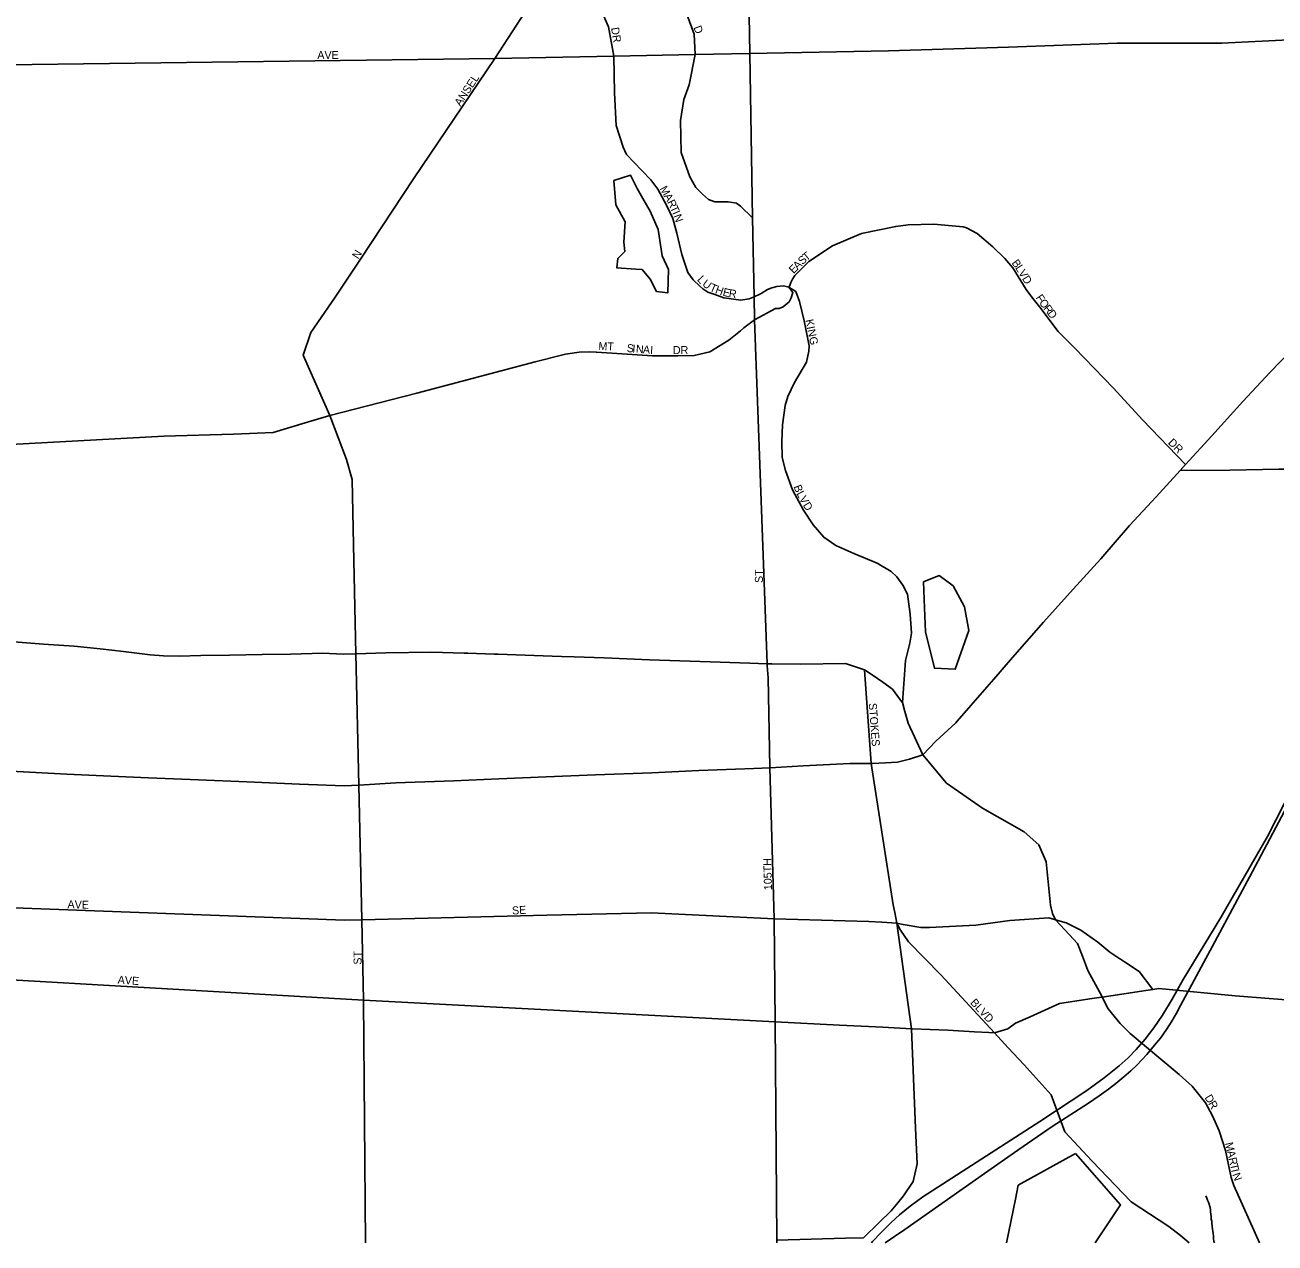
# Model space of a CAD drawing. Extents: x 2139079 to 2262683, y 1235796 to 1334992.
# Drawn here: x 2206334 to 2214145, y 1274636 to 1282247 of the extents above; entities that cross this region are included whole.
import ezdxf

# ---------------------------------------------------------------- set-up
doc = ezdxf.new("R2010")
doc.units = 0
for name, color, linetype in [('GM_P_County_Alignment', 7, 'Continuous'), ('GM_X_City_Street', 7, 'Continuous'), ('GM_X_City_Street_Text', 7, 'Continuous'), ('GM_X_Minor_Lake', 7, 'Continuous'), ('GM_X_Minor_River', 7, 'Continuous'), ('GM_X_Rail_Line', 7, 'Continuous'), ('GM_X_US_Route', 7, 'Continuous')]:
    doc.layers.add(name, color=color, linetype=linetype)

msp = doc.modelspace()

# ---------------------------------------------------------------- linework, layer by layer
at = {"layer": 'GM_P_County_Alignment'}
msp.add_lwpolyline([(2211031.7, 1274654.4), (2211460.5, 1274666.7), (2211573.9, 1274668.7), (2211671.9, 1274763.9), (2211746.1, 1274836.2), (2211789.1, 1274887), (2211823.4, 1274930.1), (2211884.9, 1275020), (2211909.4, 1275130.5), (2211898.6, 1275354.3), (2211874.7, 1275974.6), (2211782.7, 1276635.3)], dxfattribs=at)
at = {"layer": 'GM_X_City_Street'}
for points in [[(2210972.8, 1278241.7), (2210972, 1278255.2), (2210892.3, 1280405), (2210889.7, 1280548.6), (2210881, 1281042.6), (2210862.8, 1282067.9), (2210825, 1284197), (2210780.6, 1287483.9)], [(2209270.3, 1282037), (2209432.8, 1282288), (2209595.7, 1282515.8), (2209677.2, 1282890.1), (2209742.5, 1283166.8), (2209752.1, 1283253), (2209726.2, 1283296.9), (2208926.9, 1283918)], [(2210933.5, 1280568.8), (2210926.7, 1280564.6), (2210889.7, 1280548.6), (2210859.1, 1280535.3), (2210807.1, 1280526.4), (2210700.5, 1280542.6), (2210643.9, 1280562.9), (2210601.6, 1280576.7), (2210569, 1280597.8), (2210550, 1280614.7), (2210509, 1280653.6), (2210476, 1280701.1), (2210437.6, 1280812.6), (2210406.8, 1280946.4), (2210382.8, 1281038.1), (2210345.2, 1281117.6), (2210288.9, 1281220.7), (2210245.6, 1281280), (2210188.4, 1281337), (2210092.1, 1281437.3), (2210072.8, 1281482.5), (2210028.2, 1281618.7), (2210017, 1281821.9), (2210013.1, 1282051.4), (2209981.3, 1282234.9), (2209883.1, 1282460.4)], [(2210881, 1281042.6), (2210804.8, 1281114.2), (2210779.7, 1281133.2), (2210728.9, 1281141), (2210644.1, 1281141), (2210605, 1281156.6), (2210568.2, 1281190.1), (2210525.2, 1281231.4), (2210487.9, 1281297.3), (2210434.3, 1281449.1), (2210429.8, 1281650), (2210451, 1281781.7), (2210483.4, 1281873.3), (2210522.2, 1282061.3), (2210514.6, 1282190.3), (2210442.1, 1282386.7)], [(2209270.3, 1282037), (2209270.3, 1282037), (2210013.1, 1282051.4), (2210522.2, 1282061.3), (2210862.8, 1282067.9), (2211729.6, 1282084.6), (2212480.7, 1282108.6), (2213159.1, 1282132.6), (2213813.3, 1282132.4), (2214273.8, 1282156.6), (2214283.9, 1282105.5)], [(2202934.1, 1281951.1), (2204247.1, 1281973.2), (2205000.4, 1281982.7), (2205895, 1281994.1), (2209270.3, 1282037)], [(2208257.5, 1280525), (2208258.7, 1280526.8), (2208434, 1280789.6), (2208761.2, 1281286.2), (2209270.3, 1282037)], [(2210892.3, 1280405), (2211024.7, 1280475.3), (2211046.8, 1280475.3), (2211072.2, 1280485.8), (2211109.1, 1280516.4), (2211122.8, 1280542.7), (2211132.3, 1280574.4), (2211108.1, 1280609.1), (2211112.5, 1280619.4), (2211116.7, 1280631.7), (2211119.1, 1280638.4), (2211130.5, 1280658.9), (2211143.9, 1280680.5), (2211160.4, 1280698), (2211232.4, 1280769), (2211380.5, 1280867.7), (2211561.4, 1280943), (2211775.6, 1280988.4), (2211852.2, 1280997.9), (2212013.7, 1281003.1), (2212196.9, 1280984.9), (2212218, 1280978.6), (2212284.9, 1280942.8), (2212382.8, 1280859.8), (2212456.4, 1280788.6), (2212507, 1280729.5), (2212590.5, 1280593.7)], [(2211818, 1278012.4), (2211836.4, 1278276.2), (2211864.2, 1278383.1), (2211872.9, 1278447.4), (2211864.5, 1278565.6), (2211847.9, 1278689.6), (2211820.6, 1278747.2), (2211781.5, 1278798.6), (2211746.8, 1278832), (2211659.5, 1278884.3), (2211514.1, 1278943.5), (2211400.8, 1278995.3), (2211325.6, 1279045.9), (2211259.9, 1279122.8), (2211197.9, 1279215.7), (2211129.2, 1279342.7), (2211086.6, 1279462.2), (2211064.9, 1279543.9), (2211062.8, 1279644.2), (2211066.7, 1279748.6), (2211083.5, 1279869.2), (2211101.5, 1279925.1), (2211142.7, 1280012.6), (2211216.6, 1280139.2), (2211231.4, 1280207.8), (2211233.5, 1280242.6), (2211202.4, 1280399), (2211174.2, 1280518.8), (2211151, 1280580.6), (2211108.1, 1280609.1), (2211073.2, 1280616.6), (2211032.7, 1280612.3), (2211001.5, 1280605), (2210974.4, 1280593.5), (2210933.5, 1280568.8)], [(2212590.5, 1280593.7), (2212590.9, 1280593.2), (2212593.8, 1280588.5), (2212635.1, 1280535.5), (2212676.7, 1280483), (2212789.6, 1280332.2), (2212895.1, 1280226.7), (2213136.2, 1279977.8), (2213316.8, 1279778.7), (2213586.8, 1279500.2)], [(2208237.8, 1279806.9), (2208073.1, 1280183.7), (2208120.3, 1280325), (2208249.8, 1280513.5), (2208257.5, 1280525)], [(2210355.4, 1280180.2), (2210414.2, 1280180.4), (2210516.4, 1280182.2), (2210614.3, 1280204), (2210733.3, 1280276.3), (2210804.5, 1280335.8), (2210826.2, 1280354.2), (2210892.3, 1280405)], [(2205419.6, 1279573.1), (2205635, 1279607.5), (2205936.3, 1279607.8), (2207201.4, 1279677.6), (2207637.1, 1279689.3), (2207884.5, 1279701), (2208084.7, 1279759.8), (2208237.8, 1279806.9), (2208782.5, 1279945.6), (2209521.7, 1280141), (2209712.5, 1280189.9), (2209796.2, 1280201.6), (2209859.5, 1280204.6), (2209902.3, 1280201.9)], [(2209902.3, 1280201.9), (2209904.6, 1280201.8), (2210255.9, 1280180), (2210354.8, 1280180.2), (2210355.4, 1280180.2)], [(2208460.8, 1274636.1), (2208449.7, 1276154.3), (2208438.4, 1276656.1), (2208419.5, 1277497.5), (2208401.1, 1278318.3), (2208385.8, 1278997.7), (2208377.6, 1279406.5), (2208342, 1279530.8), (2208237.8, 1279806.9)], [(2210987.8, 1277609.3), (2210977.4, 1278166.4), (2210972.8, 1278241.7)], [(2211580.7, 1278217.2), (2211622.4, 1277632), (2211758.5, 1276749.9), (2211769, 1276700.4), (2211782.7, 1276635.3), (2211788.8, 1276622.7)], [(2212773.3, 1276655.7), (2212773.3, 1276655.7), (2212754.2, 1276693.9), (2212743.5, 1276746.6), (2212715.9, 1277016.7), (2212669.6, 1277124.1), (2212577.8, 1277204.4), (2212316.5, 1277353.2), (2212092.6, 1277509.2), (2211944.8, 1277686.4)], [(2211015.8, 1276660.8), (2210987.9, 1277605.5), (2210987.8, 1277609.3)], [(2195316.8, 1275884.2), (2195584.4, 1275925.4), (2195898.5, 1275973.8), (2196857.5, 1276121.5), (2198055.8, 1276306.1), (2199423.7, 1276514.9), (2199975.3, 1276599.1), (2200548.3, 1276694.8), (2200960.1, 1276758.7), (2204353.6, 1276802.7), (2205985.7, 1276739.7), (2208329.5, 1276653.5), (2208438.4, 1276656.1), (2209594.3, 1276683.5), (2210249.4, 1276698.5), (2211015.8, 1276660.8), (2211607.3, 1276645.7), (2211689.1, 1276641.1), (2211782.7, 1276635.3), (2211800.4, 1276631.3)], [(2211031.9, 1274636.1), (2211031.7, 1274654.4), (2211022.8, 1276017.2), (2211015.8, 1276660.8)], [(2211800.4, 1276631.3), (2211821.9, 1276626.4), (2211931.5, 1276607.9), (2211986.4, 1276606.6), (2212275.9, 1276621.7), (2212489.2, 1276652.2), (2212733, 1276667.3), (2212773.3, 1276655.7), (2212839.7, 1276636.8), (2212931, 1276591), (2213037.6, 1276514.8), (2213113.9, 1276453.8), (2213176.3, 1276412.1), (2213179.8, 1276409.8)], [(2212961.4, 1276378.4), (2212954.7, 1276395.9), (2212942.5, 1276427.7), (2212910.8, 1276507.3), (2212861.6, 1276562.5), (2212773.3, 1276655.7)], [(2211788.8, 1276622.7), (2211804.8, 1276589.9), (2211854.3, 1276518.4), (2212057.6, 1276311.5), (2212391.8, 1275950.1)], [(2195173.4, 1275563.7), (2195259.9, 1275543.1), (2195320.8, 1275531.8), (2195348.8, 1275529.9), (2195377.3, 1275531.8), (2196923.8, 1275769.9), (2197062.7, 1275778.9), (2197588.4, 1275813.1), (2197889.7, 1275856.3), (2199487.9, 1276121.4), (2200965.1, 1276364.1), (2204362.3, 1276390.1), (2205993.3, 1276295), (2208449.7, 1276154.3), (2211022.8, 1276017.2), (2211423.6, 1275997.3), (2211694.1, 1275984), (2211874.7, 1275974.6), (2211880.2, 1275974.3), (2212100, 1275965.1), (2212268.1, 1275954.8), (2212357.1, 1275951.5)], [(2214048.2, 1274636.1), (2213887.9, 1274995.1), (2213871.4, 1275045.1), (2213836, 1275213.4), (2213796.8, 1275337.5), (2213754, 1275431.4), (2213711.2, 1275511.4), (2213628.2, 1275615), (2213547.4, 1275688.6), (2213240.8, 1275945), (2213178.2, 1276008.6), (2213103.3, 1276098.3), (2213065.4, 1276172.6), (2213060.5, 1276182.3), (2212976.6, 1276338.7), (2212961.4, 1276378.4)], [(2213179.8, 1276409.8), (2213205.2, 1276392.9), (2213296.7, 1276331.9), (2213382.1, 1276220.8)], [(2213032.7, 1276167.6), (2213065.4, 1276172.6), (2213311.4, 1276210.1), (2213337.5, 1276214.1)], [(2213337.5, 1276214.1), (2213382.1, 1276220.8), (2213419.2, 1276226.5), (2213896.2, 1276179.9), (2214242.7, 1276154.3), (2214292.4, 1276150.6), (2214344.4, 1276150.8), (2214360.8, 1276150.8)], [(2212357.1, 1275951.5), (2212391.8, 1275950.1), (2212476.2, 1275974.6), (2212523.3, 1276009.3), (2212616.1, 1276049.6), (2212798.1, 1276131.9), (2213003.4, 1276163.2), (2213032.7, 1276167.6)], [(2212391.8, 1275950.1), (2212478.7, 1275855.8), (2212577.8, 1275749.3), (2212746.2, 1275561), (2212831.4, 1275329.9), (2213003.7, 1275146.8), (2213246.4, 1274893.7), (2213482, 1274738.8), (2213553.9, 1274682.9), (2213609.4, 1274636.1)]]:
    msp.add_lwpolyline(points, dxfattribs=at)
at = {"layer": 'GM_X_Minor_Lake'}
msp.add_line((2212523.2, 1274910.1), (2212467.9, 1274636.1), dxfattribs=at)
for points in [[(2210194.7, 1281162), (2210160.1, 1281224), (2210118.3, 1281307.6), (2210014.5, 1281275.4)], [(2210014.5, 1281275.4), (2210025.6, 1281123), (2210084, 1281017.7), (2210076.6, 1280889), (2210081.8, 1280830.8), (2210038.5, 1280787.8), (2210031.7, 1280729.4), (2210150.3, 1280721.7), (2210190.5, 1280718.4), (2210239.9, 1280659.1), (2210279.7, 1280581.6), (2210350.1, 1280572.9), (2210355.2, 1280719.6), (2210315.3, 1280803.2), (2210289.8, 1280969.4), (2210241.3, 1281083), (2210194.7, 1281162)], [(2211955.7, 1278605.4), (2211961.7, 1278454.8), (2212016.5, 1278226.8), (2212147.2, 1278221.3), (2212232.6, 1278464.1), (2212205.5, 1278610.2), (2212134.5, 1278741.4), (2212046.9, 1278805.9), (2211949.2, 1278767.9)], [(2211949.2, 1278767.9), (2211955.7, 1278605.4)], [(2212899, 1275195), (2212540.7, 1274996.8), (2212523.2, 1274910.1)], [(2213020.9, 1274636.1), (2213179.4, 1274873.6), (2212899, 1275195)]]:
    msp.add_lwpolyline(points, dxfattribs=at)
at = {"layer": 'GM_X_Minor_River'}
msp.add_lwpolyline([(2213712.6, 1274931.7), (2213718.9, 1274915.7), (2213723.1, 1274903.7), (2213729.3, 1274891.8), (2213739.9, 1274857.8), (2213742.2, 1274843.8), (2213742.4, 1274831.7), (2213744.6, 1274815.7), (2213746.9, 1274801.6), (2213747.1, 1274785.6), (2213751.4, 1274771.6), (2213751.6, 1274759.5), (2213754.2, 1274723.4), (2213756.4, 1274709.3), (2213758.6, 1274695.3), (2213760.9, 1274679.3), (2213761.1, 1274667.2), (2213763.5, 1274645.2), (2213768.2, 1274636.1)], dxfattribs=at)
at = {"layer": 'GM_X_Rail_Line'}
for points in [[(2211623.3, 1274636.1), (2211630.3, 1274645.1), (2211684.2, 1274702.2), (2211745.7, 1274764.9), (2211799.6, 1274813.1), (2211865.5, 1274865.8), (2211944.8, 1274924.1), (2212675.8, 1275395.8), (2212968.8, 1275587.9), (2213078.5, 1275667.2), (2213171.7, 1275742.7), (2213228.1, 1275792.8), (2213277.6, 1275844.1), (2213334, 1275908.8), (2213389.2, 1275981.1), (2213442.8, 1276059.8), (2213503.3, 1276159.9), (2213571.1, 1276282.2), (2213805.9, 1276669.9), (2214098.2, 1277175.5), (2214627.7, 1278213.7)], [(2211708.8, 1274636.1), (2211831.7, 1274719.6), (2212330.3, 1275070.5), (2212539, 1275216.1), (2212753.8, 1275363.2), (2212979.4, 1275510.2), (2213045.8, 1275555.6), (2213105.4, 1275597.6), (2213150.1, 1275632.1), (2213200.9, 1275673.4), (2213243.6, 1275712.1), (2213282.9, 1275748), (2213343.9, 1275813), (2213393.3, 1275871.9), (2213429.2, 1275916), (2213467.2, 1275970.9), (2213499.7, 1276023), (2213529.5, 1276071.8), (2213555.9, 1276119.2), (2213769.3, 1276518.9), (2214005.8, 1276956.6), (2214240.8, 1277400.3)]]:
    msp.add_lwpolyline(points, dxfattribs=at)
at = {"layer": 'GM_X_US_Route'}
for points in [[(2213553.3, 1279463.5), (2213553.3, 1279463.5), (2213586.8, 1279500.2), (2213750, 1279679.5), (2213944.6, 1279893.5), (2214115.5, 1280077.2), (2214240.7, 1280206.5), (2214381.7, 1280351.9), (2214514.9, 1280493.3), (2214679.8, 1280669), (2214762.6, 1280755.5)], [(2213553.3, 1279463.5), (2213864, 1279465.8), (2214168.7, 1279472.1), (2214242.7, 1279472)], [(2212388.4, 1278159.7), (2212504.8, 1278294.6), (2212699.4, 1278514.6), (2212884.1, 1278720.5), (2213056.9, 1278910.3), (2213235.5, 1279120.2), (2213402.4, 1279297.9), (2213553.3, 1279463.5)], [(2206263.4, 1278392.5), (2206449.8, 1278378.8), (2206640.2, 1278365.2), (2206802.6, 1278349.2), (2206949, 1278331), (2207115.4, 1278311.1), (2207199.6, 1278304.1), (2207297.8, 1278303.3), (2207431.8, 1278307.1), (2207612, 1278309.3), (2207816.2, 1278313.9), (2207992.4, 1278316.1), (2208194.5, 1278320.7), (2208322.7, 1278316.3), (2208401.1, 1278318.3), (2208589.6, 1278323.2), (2208874.2, 1278327.4), (2209077.7, 1278321.7)], [(2209077.7, 1278321.7), (2209100.8, 1278321), (2209264.8, 1278315.4), (2209291.3, 1278314.5), (2209628.2, 1278303), (2209685.8, 1278300.9), (2209766.1, 1278298.1)], [(2209766.1, 1278298.1), (2209953, 1278291.4), (2210235.7, 1278279.5), (2210552.6, 1278269.8), (2210863.4, 1278258.1), (2210972, 1278255.2), (2211000.6, 1278255.7), (2211180.2, 1278252.5), (2211461.1, 1278257), (2211561.1, 1278223.7)], [(2211561.1, 1278223.7), (2211580.7, 1278217.2), (2211627.8, 1278186.4), (2211694.8, 1278141.1), (2211754.6, 1278095.8), (2211806.1, 1278028.1)], [(2212159, 1277895.8), (2212344.4, 1278108.8), (2212388.4, 1278159.7)], [(2211806.1, 1278028.1), (2211818, 1278012.4), (2211832.5, 1277958.1), (2211852.4, 1277883.8), (2211944.8, 1277686.4)], [(2211944.8, 1277686.4), (2212025.7, 1277771.1), (2212150.4, 1277885.8), (2212159, 1277895.8)], [(2211630.8, 1277632.4), (2211711.1, 1277635.6), (2211786.7, 1277641.5), (2211860.7, 1277660.1), (2211944.8, 1277686.4)], [(2205971.3, 1277594.8), (2206285.8, 1277582.7), (2206594.3, 1277566.5), (2206870.8, 1277554), (2207105.2, 1277542.9), (2207417.7, 1277530.8), (2207720.3, 1277516.6), (2208048.8, 1277502.7), (2208328.4, 1277492), (2208419.5, 1277497.5), (2208650.6, 1277511.6), (2209013.3, 1277524.3), (2209295.9, 1277536.5), (2209590.5, 1277548.8), (2209899.1, 1277561.1), (2210251.7, 1277573.8), (2210544.3, 1277588), (2210889, 1277600.7), (2210987.9, 1277605.5), (2210990.1, 1277605.6)], [(2210990.1, 1277605.6), (2211197.5, 1277617), (2211488.1, 1277631.2), (2211622.4, 1277632), (2211630.8, 1277632.4)]]:
    msp.add_lwpolyline(points, dxfattribs=at)

# ---------------------------------------------------------------- texts
at = {"layer": 'GM_X_City_Street_Text'}
for s, rotation, p in [('DR', 278.96732, (2209995.9, 1282228.5)), ('D', 290.4448, (2210510.6, 1282231.8)), ('AVE', 0.00001, (2208160.6, 1282034.1)), ('ANSEL', 56.65908, (2209054.7, 1281735)), ('M', 299.39248, (2210298.4, 1281224.1)), ('A', 299.42371, (2210324.3, 1281178.1)), ('R', 296.8366, (2210345.6, 1281140.3)), ('T', 294.05959, (2210363.2, 1281105.5)), ('I', 293.33641, (2210377.5, 1281073.6)), ('N', 290.10075, (2210386, 1281054.1)), ('N', 57.98724, (2208416.6, 1280780.1)), ('S', 44.40097, (2211193.1, 1280745.2)), ('T', 38.72807, (2211217.3, 1280768.9)), ('E', 44.88409, (2211137.1, 1280689.3)), ('A', 44.91964, (2211162.1, 1280714.2)), ('B', 306.34525, (2212497.2, 1280759.4)), ('L', 302.95516, (2212520.2, 1280728.1)), ('V', 302.17451, (2212539.3, 1280698.7)), ('L', 312.31412, (2210530.8, 1280653.3)), ('U', 323.60881, (2210562.3, 1280620.2)), ('D', 302.20051, (2212562.7, 1280661.5)), ('T', 335.99572, (2210607.7, 1280588.3)), ('H', 340.02309, (2210643.4, 1280572.5)), ('E', 346.9552, (2210691, 1280555.7)), ('R', 351.37611, (2210729.4, 1280547)), ('F', 303.84161, (2212647.6, 1280542.7)), ('O', 305.56775, (2212668.1, 1280512.1)), ('R', 308.22933, (2212695.2, 1280474.2)), ('KING', 281.63346, (2211210.2, 1280403)), ('D', 308.27373, (2212719.8, 1280443.1)), ('MT', 357.27517, (2209916.6, 1280216.9)), ('S', 355.40429, (2210092.9, 1280203.7)), ('I', 355.40461, (2210128, 1280200.8)), ('N', 355.40993, (2210150, 1280199.1)), ('A', 355.42061, (2210193.8, 1280195.6)), ('I', 357.43384, (2210239.6, 1280191.9)), ('DR', 0.00001, (2210382.6, 1280190.5)), ('DR', 315, (2213473.6, 1279633.3)), ('B', 290.96254, (2211136, 1279362.4)), ('L', 298.11626, (2211153, 1279319.3)), ('V', 298.89328, (2211169.9, 1279287.6)), ('D', 302.72424, (2211193, 1279246)), ('ST', 90, (2210945.2, 1278759.9)), ('STOKES', 274.40064, (2211606.3, 1278008.2)), ('105TH', 91.46795, (2211002.3, 1276841.2)), ('AVE', 358.53192, (2206598.8, 1276727.7)), ('SE', 3.57463, (2209378.8, 1276688.1)), ('ST', 90, (2208437.2, 1276375.1)), ('AVE', 356.05688, (2206911.6, 1276256.9)), ('BLVD', 312.88011, (2212237.4, 1276135.1)), ('D', 301.88956, (2213703.4, 1275544.7)), ('R', 299.13952, (2213726.3, 1275507.8)), ('M', 282.97141, (2213832.5, 1275259.6)), ('A', 282.96023, (2213844.4, 1275208.1)), ('R', 282.97948, (2213854.3, 1275165.2)), ('T', 282.9762, (2213863.2, 1275126.6)), ('I', 282.96513, (2213871.1, 1275092.3)), ('N', 289.9236, (2213877.9, 1275064.5))]:
    msp.add_text(s, height=50, rotation=rotation, dxfattribs=at).set_placement(p)

doc.saveas('drawing.dxf')
